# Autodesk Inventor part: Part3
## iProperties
Created: 2018-06
Part Number: Part3
Document SubType Name: Modeling
Designer: M.Shelton
Density: 1 g/cm^3
Author: M.Shelton
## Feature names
1. Extrusion1
2. Chamfer2
3. Chamfer3
4. Chamfer4
